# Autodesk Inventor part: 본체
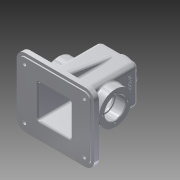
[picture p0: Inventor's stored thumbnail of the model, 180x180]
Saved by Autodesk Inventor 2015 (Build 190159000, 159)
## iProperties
Created: 2016-02
Part Number: 본체
Material: 알루미늄 6061
Document SubType Name: Modeling
Designer: Administrator
Density: 2.7 g/cm^3
Appearance: 알루미늄 - 평지
Mass: 797.447 g
Surface Area: 911.36 cm^2
Volume: 295.351 cm^3
Author: Administrator
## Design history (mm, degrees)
sketch "스케치1"
  geometry: L1 (65, 57.5)-(-65, 57.5); L2 (-65, 57.5)-(-65, -57.5); L3 (-65, -57.5)-(65, -57.5); L4 (65, -57.5)-(65, 57.5); L5 (65, 57.5)-(-65, -57.5); L6 (-65, 57.5)-(65, -57.5); 1 further point
  constraints: 12 end point, 2 midpoint, 2 parallel, 1 horizontal, 1 perpendicular
  dimensions: "d0" = 130 distance of L2.end L3.end; "d1" = 115 distance of L1.end L2.end
extrude "돌출1" new body sketch "스케치1" distance "d2" = 8; taper "d3" = 0 deg
sketch "스케치2"
  geometry: L1 (-60, 52.5)-(60, 52.5); L2 (60, 52.5)-(60, -52.5); L3 (60, -52.5)-(-60, -52.5); L4 (-60, -52.5)-(-60, 52.5); L5 (-60, 52.5)-(60, -52.5); L6 (60, 52.5)-(-60, -52.5); 1 further point
  constraints: 12 end point, 2 midpoint, 2 parallel, 1 horizontal, 1 perpendicular
  dimensions: "d4" = 120 distance of L2.end L3.end; "d5" = 105 distance of L1.end L2.end
extrude "돌출2" join sketch "스케치2" distance "d6" = 2; taper "d7" = 0 deg
sketch "스케치3"
  geometry: L1 (-65, -57.5)-(-65, 57.5) reference; L2 (-65, 57.5)-(65, 57.5) reference; L3 (65, 57.5)-(65, -57.5) reference; L4 (65, -57.5)-(-65, -57.5) reference; L5 (-32.5, -32.5)-(32.5, -32.5); L6 (32.5, -32.5)-(32.5, 32.5); L7 (32.5, 32.5)-(-32.5, 32.5); L8 (-32.5, 32.5)-(-32.5, -32.5); L9 (-32.5, -32.5)-(32.5, 32.5); L10 (32.5, -32.5)-(-32.5, 32.5); 1 further point
  constraints: 12 end point, 2 midpoint, 2 parallel, 1 horizontal, 1 perpendicular
  dimensions: "d8" = 65 distance of L6.end L7.end; "d9" = 65 distance of L5.end L6.end
extrude "돌출3" join sketch "스케치3" distance "d10" = 100; taper "d11" = 0 deg
sketch "스케치4"
  geometry: L1 (90, 0)-(90, -8) reference; L2 (90, -8)-(85, -8) reference; L3 (85, -8)-(85, -10) reference; L4 (85, -10)-(-20, -10) reference; L5 (-20, -10)-(-20, -8) reference; L6 (-20, -8)-(-25, -8) reference; L7 (-25, -8)-(-25, 0) reference; L8 (-25, 0)-(0, 0) reference; L9 (0, 0)-(65, 0) reference; L10 (65, 0)-(90, 0) reference; L11 (0, 0)-(0, 100) reference; L12 (0, 100)-(65, 100) reference; L13 (65, 100)-(65, 0) reference; L14 (-45.844, 45)-(144.35, 45); L15 (32.5, -8)-(32.5, 115.306); C1 r 27.5 at (32.5, 45)
  constraints: 4 end point, 2 point on line, 1 centre point, 1 horizontal, 1 vertical
  dimensions: "d12" = 55 distance between parallel lines of L4 L14; "d13" = 55 diameter of C1
extrude "돌출4" join sketch "스케치4" distance "d14" = 15; taper "d15" = 0 deg
sketch "스케치5"
  geometry: L1 (-25, -8)-(-25, 0) reference; L2 (-25, 0)-(0, 0) reference; L3 (0, 0)-(0, 100) reference; L4 (0, 100)-(65, 100) reference; L5 (65, 100)-(65, 0) reference; L6 (65, 0)-(90, 0) reference; L7 (90, 0)-(90, -8) reference; L8 (90, -8)-(85, -8) reference; L9 (85, -8)-(85, -10) reference; L10 (85, -10)-(-20, -10) reference; L11 (-20, -10)-(-20, -8) reference; L12 (-20, -8)-(-25, -8) reference; L13 (0, 0)-(65, 0) reference; L14 (-28.845, 45)-(133.756, 45); L15 (32.5, -8)-(32.5, 125.406); C1 r 27.5 at (32.5, 45)
  constraints: 4 end point, 2 point on line, 1 centre point, 1 horizontal, 1 vertical
  dimensions: "d16" = 55 distance between parallel lines of L10 L14; "d17" = 55 diameter of C1
extrude "돌출5" join sketch "스케치5" distance "d18" = 15; taper "d19" = 0 deg
sketch "스케치6"
  geometry: L1 (-32.5, -32.5)-(-32.5, 32.5) reference; L2 (-32.5, 32.5)-(32.5, 32.5) reference; L3 (32.5, 32.5)-(32.5, -32.5) reference; L4 (32.5, -32.5)-(-32.5, -32.5) reference; C1 r 20 at (0, 0); 1 further point
  constraints: 1 centre point, 1 coincident
  dimensions: "d21" = 40 diameter of C1
extrude "돌출6" join sketch "스케치6" distance "d22" = 10; taper "d23" = 0 deg
sketch "스케치7"
  geometry: C1 r 20 at (0, 0) reference; C2 r 10.5 at (0, 0); 1 further point
  constraints: 1 centre point, 1 coincident
  dimensions: "d24" = 21 diameter of C2
extrude "돌출7" cut sketch "스케치7" distance "d25" = 500; taper "d26" = 0 deg
sketch "스케치8" dims "d27" = 29
  geometry: C1 r 10.5 at (0, 0) reference; C2 r 20 at (0, 0) reference; 3 further points
  constraints: 2 vertical alignment, 1 coincident, 2 other
hole "구멍1" sketch "스케치8" at (0, 14.5) diameter "d28" = 2.459; stored, may be unused: countersink angle "d32" = 90 deg, drill point angle "d34" = 118 deg; dims "d29" = 7, "d30" = 4, "d31" = 2, "d33" = 9
sketch "스케치9"
  geometry: L1 (-27.5, -27.5)-(27.5, -27.5); L2 (27.5, -27.5)-(27.5, 27.5); L3 (27.5, 27.5)-(-27.5, 27.5); L4 (-27.5, 27.5)-(-27.5, -27.5); L5 (-27.5, -27.5)-(27.5, 27.5); L6 (27.5, -27.5)-(-27.5, 27.5); 1 further point
  constraints: 12 end point, 2 midpoint, 2 parallel, 1 horizontal, 1 perpendicular
  dimensions: "d38" = 55 distance of L2.end L3.end; "d39" = 55 distance of L1.end L2.end
extrude "돌출8" cut sketch "스케치9" distance "d40" = 105; taper "d41" = 0 deg
sketch "스케치10"
  geometry: L1 (57.5, -45)-(57.5, -53) reference; L2 (57.5, -53)-(52.5, -53) reference; L3 (52.5, -53)-(52.5, -55) reference; L4 (52.5, -55)-(-52.5, -55) reference; L5 (-52.5, -55)-(-52.5, -53) reference; L6 (-52.5, -53)-(-57.5, -53) reference; L7 (-57.5, -53)-(-57.5, -45) reference; L8 (-57.5, -45)-(57.5, -45) reference; C1 r 27.5 at (0, 0) reference; C2 r 17.5 at (0, 0); 1 further point
  constraints: 1 centre point, 1 coincident
  dimensions: "d42" = 35 diameter of C2
extrude "돌출9" cut sketch "스케치10" distance "d43" = 17; taper "d44" = 0 deg
sketch "스케치11"
  geometry: L1 (57.5, -45)-(57.5, -53) reference; L2 (57.5, -53)-(52.5, -53) reference; L3 (52.5, -53)-(52.5, -55) reference; L4 (52.5, -55)-(-52.5, -55) reference; L5 (-52.5, -55)-(-52.5, -53) reference; L6 (-52.5, -53)-(-57.5, -53) reference; L7 (-57.5, -53)-(-57.5, -45) reference; L8 (-57.5, -45)-(-32.5, -45) reference; L9 (-32.5, -45)-(-32.5, 55) reference; L10 (-32.5, 55)-(32.5, 55) reference; L11 (32.5, 55)-(32.5, -45) reference; L12 (32.5, -45)-(57.5, -45) reference; C1 r 17.5 at (0, 0) reference; C2 r 15 at (0, 0); 1 further point
  constraints: 1 centre point, 1 coincident
  dimensions: "d45" = 30 diameter of C2
extrude "돌출10" cut sketch "스케치11" distance "d46" = 3; taper "d47" = 0 deg
sketch "스케치12"
  geometry: L1 (-57.5, -53)-(-57.5, -45) reference; L2 (-57.5, -45)-(57.5, -45) reference; L3 (57.5, -45)-(57.5, -53) reference; L4 (57.5, -53)-(52.5, -53) reference; L5 (52.5, -53)-(52.5, -55) reference; L6 (52.5, -55)-(-52.5, -55) reference; L7 (-52.5, -55)-(-52.5, -53) reference; L8 (-52.5, -53)-(-57.5, -53) reference; C1 r 27.5 at (0, 0) reference; C2 r 17.5 at (0, 0); 1 further point
  constraints: 1 centre point, 1 coincident
  dimensions: "d48" = 35 diameter of C2
extrude "돌출11" cut sketch "스케치12" distance "d49" = 17; taper "d50" = 0 deg
sketch "스케치13"
  geometry: L1 (-57.5, -53)-(-57.5, -45) reference; L2 (-57.5, -45)-(-32.5, -45) reference; L3 (-32.5, -45)-(-32.5, 55) reference; L4 (-32.5, 55)-(32.5, 55) reference; L5 (32.5, 55)-(32.5, -45) reference; L6 (32.5, -45)-(57.5, -45) reference; L7 (57.5, -45)-(57.5, -53) reference; L8 (57.5, -53)-(52.5, -53) reference; L9 (52.5, -53)-(52.5, -55) reference; L10 (52.5, -55)-(-52.5, -55) reference; L11 (-52.5, -55)-(-52.5, -53) reference; L12 (-52.5, -53)-(-57.5, -53) reference; C1 r 17.5 at (0, 0) reference; C2 r 15 at (0, 0); 1 further point
  constraints: 1 centre point, 1 coincident
  dimensions: "d51" = 30 diameter of C2
extrude "돌출12" cut sketch "스케치13" distance "d52" = 3; taper "d53" = 0 deg
sketch "스케치14" dims "d54" = 42
  geometry: L1 (-57.5, -53)-(-57.5, -45) reference; L2 (-57.5, -45)-(57.5, -45) reference; L3 (57.5, -45)-(57.5, -53) reference; L4 (57.5, -53)-(52.5, -53) reference; L5 (52.5, -53)-(52.5, -55) reference; L6 (52.5, -55)-(-52.5, -55) reference; L7 (-52.5, -55)-(-52.5, -53) reference; L8 (-52.5, -53)-(-57.5, -53) reference; C1 r 17.5 at (0, 0) reference; C2 r 27.5 at (0, 0) reference; 3 further points
  constraints: 2 vertical alignment, 1 coincident, 2 other
hole "구멍2" sketch "스케치14" at (0, 21) diameter "d55" = 3.242; stored, may be unused: countersink angle "d59" = 90 deg, drill point angle "d61" = 118 deg; dims "d56" = 8, "d57" = 4, "d58" = 2, "d60" = 10
sketch "스케치15" dims "d65" = 42
  geometry: L1 (57.5, -45)-(57.5, -53) reference; L2 (57.5, -53)-(52.5, -53) reference; L3 (52.5, -53)-(52.5, -55) reference; L4 (52.5, -55)-(-52.5, -55) reference; L5 (-52.5, -55)-(-52.5, -53) reference; L6 (-52.5, -53)-(-57.5, -53) reference; L7 (-57.5, -53)-(-57.5, -45) reference; L8 (-57.5, -45)-(57.5, -45) reference; C1 r 17.5 at (0, 0) reference; C2 r 27.5 at (0, 0) reference; 3 further points
  constraints: 2 vertical alignment, 1 coincident, 2 other
hole "구멍3" sketch "스케치15" at (0, 21) diameter "d66" = 3.242; stored, may be unused: countersink angle "d70" = 90 deg, drill point angle "d72" = 118 deg; dims "d67" = 8, "d68" = 4, "d69" = 2, "d71" = 10
fillet "모깎기1" dims "d76" = 10
sketch "스케치17"
  geometry: L1 (-50, 52.5)-(50, 52.5) reference; L2 (60, 42.5)-(60, -42.5) reference; L3 (50, -52.5)-(-50, -52.5) reference; L4 (-60, -42.5)-(-60, 42.5) reference; L5 (27.5, -27.5)-(27.5, 27.5) reference; L6 (27.5, 27.5)-(-27.5, 27.5) reference; L7 (-27.5, 27.5)-(-27.5, -27.5) reference; L8 (-27.5, -27.5)-(27.5, -27.5) reference; C1 r 3 at (50, -42.5); C2 r 3 at (-50, -42.5); C3 r 3 at (-50, 42.5); C4 r 3 at (50, 42.5); A1 r 10 centre (-50, 42.5) between (-50, 52.5) and (-60, 42.5) reference; A2 r 10 centre (50, 42.5) between (60, 42.5) and (50, 52.5) reference; A3 r 10 centre (50, -42.5) between (50, -52.5) and (60, -42.5) reference; A4 r 10 centre (-50, -42.5) between (-60, -42.5) and (-50, -52.5) reference; 1 further point
  constraints: 4 centre point, 4 coincident
  dimensions: "d77" = 6 diameter of C1; "d79" = 6 diameter of C2; "d80" = 6 diameter of C3; "d81" = 6 diameter of C4
extrude "돌출13" cut sketch "스케치17" distance "d82" = 30; taper "d83" = 0 deg
sketch "스케치19"
  geometry: L1 (27.5, -27.5)-(27.5, 27.5) reference; L2 (27.5, 27.5)-(-27.5, 27.5) reference; L3 (-27.5, 27.5)-(-27.5, -27.5) reference; L4 (-27.5, -27.5)-(27.5, -27.5) reference; L5 (-32.5, -32.5)-(-32.5, 32.5) reference; L6 (-32.5, 32.5)-(32.5, 32.5) reference; L7 (32.5, 32.5)-(32.5, -32.5) reference; L8 (32.5, -32.5)-(-32.5, -32.5) reference; L9 (-65, -57.5)-(-65, 57.5) reference; L10 (-65, 57.5)-(65, 57.5) reference; L11 (65, 57.5)-(65, -57.5) reference; L12 (65, -57.5)-(-65, -57.5) reference; C1 r 3 at (-50, -42.5) reference; C2 r 3 at (50, 42.5) reference; C3 r 3 at (-50, 42.5) reference; C4 r 3 at (50, -42.5) reference; C5 r 7.5 at (50, -42.5); C6 r 7.5 at (-50, -42.5); C7 r 7.5 at (-50, 42.5); C8 r 7.5 at (50, 42.5); 1 further point
  constraints: 4 centre point, 4 coincident, 3 equal radius
  dimensions: "d84" = 15 diameter of C5
extrude "돌출14" join sketch "스케치19" distance "d85" = 3; taper "d86" = 0 deg
sketch "스케치20"
  geometry: L1 (-22.5, 15)-(-22.5, 70) reference; L2 (-22.5, 70)-(-77.5, 70) reference; L3 (-77.5, 70)-(-77.5, 15) reference; L4 (-77.5, 15)-(-22.5, 15) reference; L5 (-82.5, 10)-(-82.5, 75) reference; L6 (-82.5, 75)-(-17.5, 75) reference; L7 (-17.5, 75)-(-17.5, 10) reference; L8 (-17.5, 10)-(-82.5, 10) reference; C1 r 7.5 at (-100, 85) reference; C2 r 7.5 at (0, 0) reference; C3 r 7.5 at (-100, 0) reference; C4 r 7.5 at (0, 85) reference; C5 r 3 at (0, 0); C6 r 3 at (-100, 0); C7 r 3 at (-100, 85); C8 r 3 at (0, 85); 1 further point
  constraints: 4 centre point, 4 coincident
  dimensions: "d87" = 6 diameter of C6; "d88" = 6 diameter of C7; "d89" = 6 diameter of C8; "d90" = 6 diameter of C5
extrude "돌출15" cut sketch "스케치20" distance "d91" = 3; taper "d92" = 0 deg
sketch "스케치21"
  geometry: L1 (8, -57.5)-(0, -57.5) reference; L2 (0, -57.5)-(0, -52.5) reference; L3 (0, -52.5)-(-2, -52.5) reference; L4 (-2, -52.5)-(-2, -27.5) reference; L5 (-2, -27.5)-(103, -27.5) reference; L6 (103, -27.5)-(103, -10.5) reference; L7 (103, -10.5)-(118, -10.5) reference; L8 (118, -10.5)-(118, -13.271) reference; L9 (118, -13.271)-(109, -13.271) reference; L10 (109, -13.271)-(108.261, -14.5) reference; L11 (108.261, -14.5)-(109, -15.73) reference; L12 (109, -15.73)-(118, -15.73) reference; L13 (118, -15.73)-(118, -20) reference; L14 (118, -20)-(108, -20) reference; L15 (108, -20)-(108, -32.5) reference; L16 (108, -32.5)-(8, -32.5) reference; L17 (8, -32.5)-(8, -57.5) reference; L18 (0, 57.5)-(8, 57.5) reference; L19 (8, 57.5)-(8, 32.5) reference; L20 (8, 32.5)-(108, 32.5) reference; L21 (108, 32.5)-(108, 20) reference; L22 (108, 20)-(118, 20) reference; L23 (118, 20)-(118, 15.73) reference; L24 (118, 15.73)-(109, 15.73) reference; L25 (109, 15.73)-(108.261, 14.5) reference; L26 (108.261, 14.5)-(109, 13.271) reference; L27 (109, 13.271)-(118, 13.271) reference; L28 (118, 13.271)-(118, 10.5) reference; L29 (118, 10.5)-(103, 10.5) reference; L30 (103, 10.5)-(103, 27.5) reference; L31 (103, 27.5)-(-2, 27.5) reference; L32 (-2, 27.5)-(-2, 52.5) reference; L33 (-2, 52.5)-(0, 52.5) reference; L34 (0, 52.5)-(0, 57.5) reference; L35 (8, 32.5)-(108, 32.5) reference; L36 (93.069, 32.5)-(8, 47.5); L37 (8, -57.5)-(8, 57.5) reference; L38 (8, 32.5)-(93.069, 32.5); L39 (8, 32.5)-(8, 47.5); 1 further point
  constraints: 6 end point, 2 point on line, 1 collinear, 1 vertical
  dimensions: "d95" = 10 deg angle of L36 L18; "d96" = 10 distance of L18.end L36.end
extrude "돌출16" join sketch "스케치21" stored distance "d97" = 10; taper "d98" = 0 deg
sketch "스케치22"
  geometry: L1 (108, 20)-(118, 20) reference; L2 (118, 20)-(118, 15.73) reference; L3 (118, 15.73)-(109, 15.73) reference; L4 (109, 15.73)-(108.261, 14.5) reference; L5 (108.261, 14.5)-(109, 13.271) reference; L6 (109, 13.271)-(118, 13.271) reference; L7 (118, 13.271)-(118, 10.5) reference; L8 (118, 10.5)-(103, 10.5) reference; L9 (103, 10.5)-(103, 27.5) reference; L10 (103, 27.5)-(-2, 27.5) reference; L11 (-2, 27.5)-(-2, 52.5) reference; L12 (-2, 52.5)-(0, 52.5) reference; L13 (0, 52.5)-(0, 57.5) reference; L14 (0, 57.5)-(8, 57.5) reference; L15 (8, 57.5)-(8, 47.5) reference; L16 (8, 47.5)-(93.069, 32.5) reference; L17 (93.069, 32.5)-(108, 32.5) reference; L18 (108, 32.5)-(108, 20) reference; L19 (118, -20)-(108, -20) reference; L20 (108, -20)-(108, -32.5) reference; L21 (108, -32.5)-(8, -32.5) reference; L22 (8, -32.5)-(8, -57.5) reference; L23 (8, -57.5)-(0, -57.5) reference; L24 (0, -57.5)-(0, -52.5) reference; L25 (0, -52.5)-(-2, -52.5) reference; L26 (-2, -52.5)-(-2, -27.5) reference; L27 (-2, -27.5)-(103, -27.5) reference; L28 (103, -27.5)-(103, -10.5) reference; L29 (103, -10.5)-(118, -10.5) reference; L30 (118, -10.5)-(118, -13.271) reference; L31 (118, -13.271)-(109, -13.271) reference; L32 (109, -13.271)-(108.261, -14.5) reference; L33 (108.261, -14.5)-(109, -15.73) reference; L34 (109, -15.73)-(118, -15.73) reference; L35 (118, -15.73)-(118, -20) reference; L36 (8, -32.5)-(108, -32.5) reference; L37 (93.069, -32.5)-(8, -47.5); L38 (8, -32.5)-(93.069, -32.5); L39 (8, -35)-(8, -50) reference; L40 (8, -32.5)-(8, -47.5); 1 further point
  constraints: 6 end point, 2 point on line, 1 perpendicular, 1 vertical
  dimensions: "d99" = 10 distance of L22.end L37.end; "d100" = 10 deg angle of L23 L37
extrude "돌출17" join sketch "스케치22" stored distance "d101" = 10; taper "d102" = 0 deg
sketch "스케치24"
  geometry: L1 (-20, -10)-(-20, -8) reference; L2 (-20, -8)-(-25, -8) reference; L3 (-25, -8)-(-25, 0) reference; L4 (-25, 0)-(0, 0) reference; L5 (0, 0)-(65, 0) reference; L6 (65, 100)-(65, 0) reference; L7 (0, 100)-(65, 100) reference; L8 (0, 0)-(0, 100) reference; L9 (85, -10)-(-20, -10) reference; L10 (85, -8)-(85, -10) reference; L11 (90, -8)-(85, -8) reference; L12 (90, 0)-(90, -8) reference; L13 (65, 0)-(90, 0) reference; L14 (52.5, 110)-(12.5, 110) reference; C1 r 17.5 at (32.5, 45) reference; C2 r 27.5 at (32.5, 45) reference; 2 further points
  constraints: 1 other
  dimensions: "d103" = 26 distance from line of point (32.5, 84) L14; "d104" = 32.5 distance from line of point (32.5, 84) L8
feature "엠보싱1" sketch "스케치24" dims "d105" = 0.5, "d106" = 0
fillet "모깎기2" dims "d107" = 15
fillet "모깎기4" dims "d109" = 3
fillet "모깎기6" dims "d111" = 8
fillet "모깎기7" dims "d112" = 8
fillet "모깎기10" dims "d115" = 3
fillet "모깎기11" dims "d116" = 3
fillet "모깎기12" dims "d117" = 3
fillet "모깎기13" dims "d118" = 3
fillet "모깎기14" dims "d119" = 0.3
chamfer "모따기1" distance "d120" = 1; stored, may be unused: second distance "d121" = 2, angle "d122" = 45 deg
chamfer "모따기2" distance "d123" = 1; stored, may be unused: second distance "d124" = 2, angle "d125" = 45 deg
fillet "모깎기15" dims "d126" = 3
sketch "스케치26"
  geometry: L1 (0, 92)-(49, 92) reference; L2 (49, 57.49)-(49, 92) reference; L3 (0, 0)-(0, 32.51) reference; L4 (-33, 0)-(0, 0) reference; L5 (-33, -8)-(-33, 0) reference; L6 (-28, -8)-(-33, -8) reference; L7 (-28, -10)-(-28, -8) reference; L8 (77, -10)-(-28, -10) reference; L9 (77, -8)-(77, -10) reference; L10 (82, -8)-(77, -8) reference; L11 (82, 0)-(82, -8) reference; L12 (49, 0)-(82, 0) reference; L13 (0, 0)-(49, 0) reference; L14 (0, 57.49)-(0, 92) reference; L15 (49, 0)-(49, 32.51) reference; L16 (43.489, 83.997)-(42.159, 83.997) reference; L17 (42.159, 83.997)-(42.159, 84.377) reference; L18 (42.159, 84.377)-(43.489, 84.377) reference; L19 (43.489, 84.377)-(43.489, 86.955) reference; L20 (43.489, 86.955)-(43.815, 86.955) reference; L21 (43.95, 86.69)-(43.95, 81.018) reference; L22 (43.95, 81.018)-(43.489, 81.018) reference; L23 (43.489, 81.018)-(43.489, 83.997) reference; L24 (10.558, 84.648)-(10.558, 84.254) reference; L25 (10.558, 84.254)-(9.439, 84.254) reference; L26 (9.439, 84.254)-(9.439, 82.511) reference; L27 (9.439, 82.511)-(8.964, 82.511) reference; L28 (8.964, 82.511)-(8.964, 87.002) reference; L29 (8.964, 87.002)-(9.269, 87.002) reference; L30 (9.439, 86.737)-(9.439, 84.648) reference; L31 (9.439, 84.648)-(10.558, 84.648) reference; L32 (9.656, 81.561)-(9.656, 81.181) reference; L33 (9.656, 81.181)-(5.307, 81.181) reference; L34 (5.307, 81.181)-(5.307, 82.809) reference; L35 (5.307, 82.809)-(5.66, 82.809) reference; L36 (5.769, 82.592)-(5.769, 81.561) reference; L37 (5.769, 81.561)-(9.656, 81.561) reference; L38 (7.126, 86.425)-(5.647, 86.425) reference; L39 (5.647, 86.425)-(5.647, 86.778) reference; L40 (5.647, 86.778)-(7.126, 86.778) reference; L41 (7.126, 86.778)-(7.126, 86.425) reference; L42 (4.453, 85.618)-(4.453, 85.971) reference; L43 (4.453, 85.971)-(8.218, 85.971) reference; L44 (8.218, 85.971)-(8.218, 85.618) reference; L45 (8.218, 85.618)-(4.453, 85.618) reference; L46 (21.583, 81.385)-(21.026, 82.911) reference; L47 (21.026, 82.911)-(18.774, 82.911) reference; L48 (18.774, 82.911)-(18.204, 81.385) reference; L49 (18.204, 81.385)-(17.723, 81.385) reference; L50 (17.723, 81.385)-(19.622, 86.385) reference; L51 (19.622, 86.385)-(20.165, 86.385) reference; L52 (20.165, 86.385)-(22.064, 81.385) reference; L53 (22.064, 81.385)-(21.583, 81.385) reference; L54 (19.887, 85.896)-(18.93, 83.325) reference; L55 (18.93, 83.325)-(20.864, 83.325) reference; L56 (20.864, 83.325)-(19.887, 85.896) reference; L57 (14.405, 83.149)-(16.216, 83.149) reference; L58 (16.216, 83.149)-(16.216, 81.025) reference; L59 (16.216, 81.025)-(15.755, 81.025) reference; L60 (15.755, 81.025)-(15.755, 82.775) reference; L61 (15.755, 82.775)-(11.922, 82.775) reference; L62 (11.922, 82.775)-(11.922, 83.149) reference; L63 (11.922, 83.149)-(13.95, 83.149) reference; L64 (13.95, 83.149)-(13.95, 84.37) reference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; C1 r 17.5 at (24.5, 45) reference; A1 r 27.5 centre (24.5, 45) between (49, 57.49) and (0, 57.49) reference; A2 r 27.5 centre (24.5, 45) between (0, 57.49) and (0, 32.51) reference; A3 r 27.5 centre (24.5, 45) between (49, 32.51) and (49, 57.49) reference; A4 r 27.5 centre (24.5, 45) between (0, 32.51) and (49, 32.51) reference; 64 further points
  constraints: 12 end point, 3 midpoint, 2 parallel, 1 collinear, 1 horizontal, 1 perpendicular, 1 vertical alignment, 76 other
  dimensions: "d127" = 20 distance of L116.end L117.end; "d128" = 4.41041 distance of L116.start L116.end
extrude "돌출18" join sketch "스케치26" distance "d129" = 10; taper "d130" = 0 deg
sketch "스케치27"
  geometry: L1 (0, 92)-(49, 92) reference; L2 (49, 57.49)-(49, 92) reference; L3 (0, 0)-(0, 32.51) reference; L4 (-33, 0)-(0, 0) reference; L5 (-33, -8)-(-33, 0) reference; L6 (-28, -8)-(-33, -8) reference; L7 (-28, -10)-(-28, -8) reference; L8 (77, -10)-(-28, -10) reference; L9 (77, -8)-(77, -10) reference; L10 (82, -8)-(77, -8) reference; L11 (82, 0)-(82, -8) reference; L12 (49, 0)-(82, 0) reference; L13 (0, 0)-(49, 0) reference; L14 (0, 57.49)-(0, 92) reference; L15 (49, 0)-(49, 32.51) reference; L16 (21.5, 20)-(27.5, 20); L17 (27.5, 20)-(27.5, 0); L18 (27.5, 0)-(21.5, 0); L19 (21.5, 0)-(21.5, 20); L20 (21.5, 20)-(27.5, 0); L21 (27.5, 20)-(21.5, 0); C1 r 17.5 at (24.5, 45) reference; A1 r 27.5 centre (24.5, 45) between (49, 57.49) and (0, 57.49) reference; A2 r 27.5 centre (24.5, 45) between (0, 57.49) and (0, 32.51) reference; A3 r 27.5 centre (24.5, 45) between (49, 32.51) and (49, 57.49) reference; A4 r 27.5 centre (24.5, 45) between (0, 32.51) and (49, 32.51) reference; 3 further points
  constraints: 12 end point, 3 midpoint, 2 parallel, 1 collinear, 1 horizontal, 1 perpendicular, 1 vertical alignment
  dimensions: "d131" = 20 distance of L16.end L17.end; "d132" = 6 distance of L17.end L18.end
extrude "돌출19" join sketch "스케치27" distance "d133" = 10; taper "d134" = 0 deg
fillet "모깎기16" dims "d135" = 3
fillet "모깎기17" dims "d136" = 1
fillet "모깎기18" dims "d137" = 3
node "솔리드1"
pattern_circular "원형 패턴1" dims angle "d36" = 360 deg
pattern_circular "원형 패턴2" dims angle "d63" = 360 deg
pattern_circular "원형 패턴3" dims angle "d74" = 360 deg
node "절단 모서리 투영1"
node "절단 모서리 투영2"
node "절단 모서리 투영3"
node "절단 모서리 투영4"
node "절단 모서리 투영5"
node "절단 모서리 투영6"
node "절단 모서리 투영7"
node "절단 모서리 투영8"
node "절단 모서리 투영9"
node "절단 모서리 투영10"
node "절단 모서리 투영11"
node "절단 모서리 투영12"
node "절단 모서리 투영14"
node "절단 모서리 투영15"
node "절단 모서리 투영16"
node "절단 모서리 투영17"
node "절단 모서리 투영18"
node "절단 모서리 투영20"
node "절단 모서리 투영22"
node "절단 모서리 투영23"
